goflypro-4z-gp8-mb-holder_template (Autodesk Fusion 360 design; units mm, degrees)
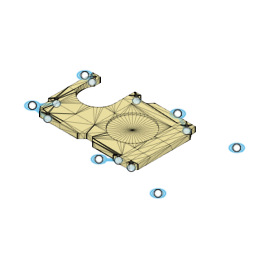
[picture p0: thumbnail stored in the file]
base_mesh_feature "Grundnetzelement"
modify "Ändern1"
modify "Ändern2"
modify "Ändern4"
modify "Ändern5"
modify "Ändern6"
sketch "Skizze" plane through (0, 0, 0) normal (0, 0, 1) x axis (1, 0, 0)
  line L1 (-43.4754, -11.5659) -> (-40.5019, -7.4733)
  line L2 (-41.152, -7.007) -> (-44.1054, -11.072)
  line L3 (-42.8621, 13.5611) -> (-41.8149, 13.2805)
  line L4 (-41.5775, 14.0451) -> (-42.7042, 14.347)
  line L5 (-42.8739, -14.4713) -> (-36.7524, -15.5507)
  line L6 (-36.6048, -14.7644) -> (-42.7064, -13.6885)
  line L7 (6.3176, 17.0075) -> (-0.3627, 20.5595)
  line L8 (-0.5976, -19.0618) -> (1.9112, -16.9567)
  line L9 (1.3986, -16.3425) -> (-1.1024, -18.4411)
  line L10 (-0.7363, 19.8521) -> (5.9318, 16.3066)
  circle C1 centre (-40.415, 13.265) radius 0.6
  circle C2 centre (-40.045, -6.15) radius 0.6
  circle C3 centre (-35.36, -15.405) radius 0.6
  circle C4 centre (9.535, -15.79) radius 0.6
  circle C5 centre (-19.98, 16.445) radius 0.6
  circle C6 centre (7.3, 16.01) radius 0.6
  circle C7 centre (-45.5, 14.5) radius 1.05
  circle C8 centre (-45.5, -13.5) radius 1.05
  circle C9 centre (-3, 21.5) radius 1.05
  circle C10 centre (28.5, 21.5) radius 1.05
  circle C11 centre (28.5, -20.5) radius 1.05
  circle C12 centre (-3, -20.5) radius 1.05
  circle C13 centre (-45.5, 14.5) radius 2
  circle C14 centre (-3, 21.5) radius 2
  circle C15 centre (28.5, 21.5) radius 2
  circle C16 centre (-45.5, -13.5) radius 2
  circle C17 centre (28.5, -20.5) radius 2
  circle C18 centre (28.5, -20.5) radius 2.8
  circle C19 centre (-45.5, -13.5) radius 2.8
  circle C20 centre (-3, 21.5) radius 2.8
  circle C21 centre (28.5, 21.5) radius 2.8
  circle C22 centre (7.3, 16.01) radius 1.4
  circle C23 centre (-19.98, 16.445) radius 1.4
  circle C24 centre (9.535, -15.79) radius 1.4
  circle C25 centre (-35.36, -15.405) radius 1.4
  circle C26 centre (-40.045, -6.15) radius 1.4
  circle C27 centre (-40.415, 13.265) radius 1.4
  circle C28 centre (-45.5, 14.5) radius 2.8
  circle C29 centre (2.685, -15.79) radius 0.6
  circle C30 centre (2.685, -15.79) radius 1.4
  circle C31 centre (-3, -20.5) radius 2
  circle C32 centre (-3, -20.5) radius 2.8
  point P30 (-43.4754, -11.5659)
  point P31 (-44.1054, -11.072)
  point P32 (-41.152, -7.007)
  point P33 (-40.5019, -7.4733)
  point P35 (-42.7042, 14.347)
  point P36 (-42.8621, 13.5611)
  point P37 (-41.8149, 13.2805)
  point P38 (-41.5775, 14.0451)
  point P39 (-36.7524, -15.5507)
  point P40 (-36.6048, -14.7644)
  point P41 (-42.8739, -14.4713)
  point P42 (-42.7064, -13.6885)
  point P47 (1.3986, -16.3425)
  point P48 (1.9112, -16.9567)
  point P49 (-0.5976, -19.0618)
  point P50 (-1.1024, -18.4411)
  point P51 (-0.3627, 20.5595)
  point P52 (-0.7363, 19.8521)
  point P53 (6.3176, 17.0075)
  point P54 (5.9318, 16.3066)
  concentric C7 C13
  concentric C9 C14
  concentric C10 C15
  concentric C11 C17
  concentric C17 C18
  concentric C9 C20
  concentric C10 C21
  concentric C6 C22
  concentric C5 C23
  concentric C4 C24
  concentric C3 C25
  concentric C2 C26
  concentric C1 C27
  coincident C19 P30
  coincident C19 P31
  coincident C26 P32
  coincident C26 P33
  concentric C7 C28
  coincident C28 P35
  coincident C28 P36
  coincident C27 P37
  coincident C27 P38
  coincident C25 P39
  coincident C25 P40
  coincident C19 P41
  coincident C19 P42
  concentric C29 C30
  concentric C12 C31
  concentric C12 C32
  coincident C30 P47
  coincident C30 P48
  coincident C32 P49
  coincident C32 P50
  coincident C20 P51
  coincident C20 P52
  coincident C22 P53
  coincident C22 P54
  dimension "d1" diameter C1 = 1.2
  dimension "d2" diameter C2 = 1.2
  dimension "d3" diameter C3 = 1.2
  dimension "d5" diameter C4 = 1.2
  dimension "d6" diameter C5 = 1.2
  dimension "d7" diameter C6 = 1.2
  dimension "d12" diameter C9 = 2.1
  dimension "d13" diameter C7 = 2.1
  dimension "d14" diameter C8 = 2.1
  dimension "d15" diameter C13 = 4
  dimension "d16" diameter C14 = 4
  dimension "d17" diameter C15 = 4
  dimension "d18" diameter C16 = 4
  dimension "d19" diameter C17 = 4
  dimension "d20" diameter C18 = 5.6
  dimension "d21" diameter C19 = 5.6
  dimension "d23" diameter C20 = 5.6
  dimension "d24" diameter C21 = 5.6
  dimension "d26" diameter C22 = 2.8
  dimension "d27" diameter C23 = 2.8
  dimension "d28" diameter C24 = 2.8
  dimension "d30" diameter C25 = 2.8
  dimension "d31" diameter C26 = 2.8
  dimension "d32" diameter C27 = 2.8
  dimension "d51" diameter C28 = 5.6
  dimension "d52" diameter C29 = 1.2
  dimension "d53" diameter C30 = 2.8
  dimension "d54" diameter C31 = 4
  dimension "d55" diameter C32 = 5.6
  dimension "d10" R-Pattern1-uDistance = 31.5
  dimension "d11" R-Pattern1-vDistance = -42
